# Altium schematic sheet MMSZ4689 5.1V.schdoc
size 127 x 101 mm
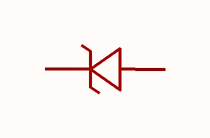
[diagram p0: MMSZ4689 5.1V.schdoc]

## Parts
D?  mmsz4689 5.1v  [SOD-123_L2.8-W1.6-LS3.7-RD]  (value not drawn)

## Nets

Not connected (* = marked no-connect by the designer): D? 1(K) 2(A)

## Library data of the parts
D? = mmsz4689 5.1v: 二极管配置:1个独立式;稳压值(标称值):5.1V;稳压值(范围):4.85V~5.36V;耗散功率(Pd):500mW;; Manufacturer: CJ(江苏长电/长晶); AddInBom: yes; ModelId: 73858e86c18848f5a81710cfe7352ee5; ModelTransform: 145.669,70.3249,0,0,0,0,0,0,0; Diode Configuration: 1个独立式; Reverse Leakage Current (Ir): 10uA@3V; Pd - Power Dissipation: 500mW; Operating Junction Temperature Range: -55℃~+150℃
